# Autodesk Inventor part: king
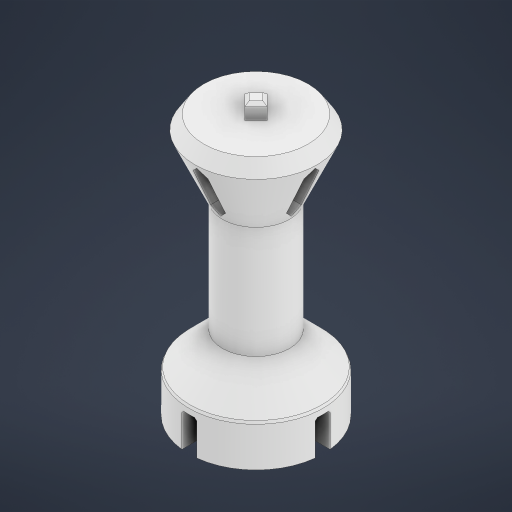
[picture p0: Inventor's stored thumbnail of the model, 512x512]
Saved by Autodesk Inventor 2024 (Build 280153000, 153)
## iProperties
Created: 2025-07
Part Number: king
Material: ABS Plastic
Document SubType Name: Modeling
Designer: acer
Density: 1.06 g/cm^3
Appearance: Smooth - White
Author: acer
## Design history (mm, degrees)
sketch "Sketch4"
  geometry: L1 (0, 0)-(35, 0); L2 (0, 0)-(0, 9); L3 (0, 9)-(5.5, 9); L4 (5.5, 9)-(10, 4.5); L5 (10, 4.5)-(25, 4.5); L6 (25, 4.5)-(35, 9); L7 (35, 9)-(35, 0)
  constraints: 14 end point, 2 vertical, 1 horizontal, 1 parallel, 1 perpendicular, 1 point on line
  dimensions: "d16" = 35 distance of L1.start L1.end; "d17" = 9 distance of L1.start L2.end; "d18" = 5.5 distance of L2.end L3.end; "d19" = 135 deg angle of L3 L4; "d20" = 15 distance of L4.end L5.end
revolve "Revolution2" sketch "Sketch4" stored, may be unused: angle "d21" = 90 deg
chamfer "Chamfer3" distance "d22" = 0.2; stored, may be unused: second distance "d23" = 2, angle "d24" = 45 deg
chamfer "Chamfer4" distance "d25" = 2; stored, may be unused: second distance "d26" = 2, angle "d27" = 45 deg
sketch "Sketch5"
  geometry: L1 (25, -4.5)-(25, 4.5) reference; L2 (41.352, 1)-(25, 1); L3 (25, 1)-(25, -1); L4 (25, -1)-(41.352, -1); L5 (41.352, -1)-(41.352, 1); L6 (33.176, -8.179)-(33.176, 8.179) reference; L7 (41.352, 1)-(25, -1); L8 (25, 1)-(41.352, -1); L9 (25, 1)-(33.176, 1); L10 (33.176, -1)-(25, -1); L11 (33.176, 0)-(31.676, 0); L12 (25, 0)-(26.5, 0); L13 (32.676, 0)-(31.676, 1); L14 (32.676, 0)-(31.676, -1); L15 (25.5, 0)-(26.5, -1); L16 (25.5, 0)-(26.5, 1); A1 r 1 centre (31.676, 0) between (32.676, 0) and (31.676, 1); A2 r 1 centre (26.5, 0) between (25.5, 0) and (26.5, -1); 5 further points
  constraints: 28 end point, 9 point on line, 6 midpoint, 6 point on circle, 3 horizontal, 2 centre point, 2 coincident, 2 parallel, 1 collinear, 1 perpendicular
  dimensions: "d28" = 2 distance of L3.end L2.end; "d29" = 1.5 distance of L11.start L11.end; "d30" = 2 diameter of A1; "d31" = 1.5 distance of L12.start L12.end; "d32" = 2 diameter of A2
extrude "Extrusion3" cut sketch "Sketch5" stored distance "d33" = 23.75; taper "d34" = 0 deg
sketch "Sketch6"
  geometry: L1 (8.179, 33.176)-(-8.179, 33.176) reference; L2 (1, 16.824)-(-1, 16.824); L3 (-1, 16.824)-(-1, 33.176); L4 (-1, 33.176)-(1, 33.176); L5 (1, 33.176)-(1, 16.824); L6 (4.5, 25)-(-4.5, 25) reference; L7 (1, 16.824)-(-1, 33.176); L8 (-1, 16.824)-(1, 33.176); L9 (0, 33.176)-(0, 31.676); L10 (0, 25)-(0, 26.5); L11 (4.725, 25.5)-(-4.725, 25.5) reference; L12 (0, 25)-(1.5, 25); L13 (-7.954, 32.676)-(7.954, 32.676) reference; L14 (0, 32.676)-(-1, 31.676); L15 (0, 32.676)-(1, 31.676); L16 (0, 25.5)-(1, 26.5); L17 (0, 25.5)-(-1, 26.5); A1 r 1 centre (0, 31.676) between (-1, 31.676) and (1, 31.676); A2 r 1 centre (0, 26.5) between (0, 25.5) and (1, 26.5); 1 further point
  constraints: 26 end point, 6 midpoint, 5 point on circle, 5 point on line, 3 perpendicular, 2 centre point, 2 coincident, 2 horizontal, 2 parallel, 1 vertical
  dimensions: "d35" = 2 distance of L3.end L4.end; "d36" = 1.5 distance of L9.start L9.end; "d37" = 1.5 distance of L10.start L10.end; "d38" = 90 deg angle of L12 L10 (derived); "d39" = 2 diameter of A1; "d40" = 2 diameter of A2
extrude "Extrusion4" cut sketch "Sketch6" stored distance "d41" = 23.75; taper "d42" = 0 deg
sketch "Sketch7"
  geometry: L1 (4.725, 0)-(0, 0) reference; L2 (0, 0)-(-4.725, 0) reference; L3 (-1.5, 0)-(0, 1.5); L4 (0, 1.5)-(1.5, 0); L5 (1.5, 0)-(0, -1.5); L6 (0, -1.5)-(-1.5, 0); A1 r 1.5 centre (0, 0) between (-1.5, 0) and (0, 1.5)
  constraints: 8 end point, 4 point on circle, 2 perpendicular, 2 point on line, 1 centre point, 1 coincident
  dimensions: "d43" = 3 diameter of A1
extrude "Extrusion5" join sketch "Sketch7" distance "d44" = 2; taper "d45" = 0 deg
chamfer "Chamfer5" distance "d46" = 0.4; stored, may be unused: second distance "d47" = 2, angle "d48" = 45 deg
sketch "Sketch8"
  geometry: L1 (9, 5.3)-(-9, 5.3) reference; L2 (1, -5.3)-(-1, -5.3); L3 (-1, -5.3)-(-1, 5.3); L4 (-1, 5.3)-(1, 5.3); L5 (1, 5.3)-(1, -5.3); L6 (1, -5.3)-(-1, 5.3); L7 (-1, -5.3)-(1, 5.3); L8 (0, 5.3)-(0, 4.3); L9 (0, 5.3)-(1, 4.3); L10 (0, 5.3)-(-1, 4.3); A1 r 1 centre (0, 4.3) between (0, 5.3) and (1, 4.3); 1 further point
  constraints: 18 end point, 3 midpoint, 3 point on circle, 3 point on line, 2 parallel, 1 centre point, 1 coincident, 1 horizontal, 1 perpendicular, 1 vertical
  dimensions: "d49" = 2 distance of L3.end L4.end; "d50" = 1 distance of L8.start L8.end
extrude "Extrusion6" cut sketch "Sketch8" stored distance "d51" = 20.75; taper "d52" = 0 deg
chamfer "Chamfer6" distance "d53" = 1; stored, may be unused: second distance "d54" = 2, angle "d55" = 45 deg
sketch "Sketch9"
  geometry: L1 (5.3, -9)-(5.3, 9) reference; L2 (-5.3, 1)-(5.3, 1); L3 (5.3, 1)-(5.3, -1); L4 (5.3, -1)-(-5.3, -1); L5 (-5.3, -1)-(-5.3, 1); L6 (-5.3, 1)-(5.3, -1); L7 (5.3, 1)-(-5.3, -1); L8 (5.3, 0)-(4.3, 0); L9 (5.3, 0)-(4.3, 1); L10 (5.3, 0)-(4.3, -1); A1 r 1 centre (4.3, 0) between (5.3, 0) and (4.3, 1); 1 further point
  constraints: 18 end point, 3 midpoint, 3 point on circle, 3 point on line, 2 horizontal, 2 parallel, 1 centre point, 1 coincident, 1 perpendicular
  dimensions: "d56" = 2 distance of L2.end L3.end; "d57" = 1 distance of L8.start L8.end
extrude "Extrusion7" cut sketch "Sketch9" stored distance "d58" = 20.75; taper "d59" = 0 deg
chamfer "Chamfer7" distance "d60" = 1; stored, may be unused: second distance "d61" = 2, angle "d62" = 45 deg
body "Solid2"
